// TIA Portal project "sample_pnio_test" (V15)

(* hardware
DEVICE "GSD device_1"  GSD.Device.PN
   slot 0: "机架"  Rack  V1.0
   slot 0: "id3000"  MV-ID3XXX  MV-IXX
      slot 0: "MV-ID3XXX"  MV-ID3XXX
      slot 1: "Interface"  Interface
         slot 1: "Port 1"  Port 1
   slot 1: " Acquisition Status _1"   Acquisition Status 
      slot 0: " Acquisition Status"   Acquisition Status 
   slot 2: " Acquisition Control _1"   Acquisition Control 
      slot 0: " Acquisition Control"   Acquisition Control 
   slot 3: " Reads Result 64 bytes _1"   Reads Result 64 bytes 
      slot 0: " Reads Result 64 bytes"   Reads Result 64 bytes 
   slot 4: " User Data 64 bytes _1"  User Data 64 bytes
      slot 0: " User Data 64 bytes"  User Data 64 bytes
DEVICE "S71500/ET200MP station_1"  S7-1500 station
   slot 0: "导轨_0"  Rack  6ES7 590-1***0-0AA0
   slot 1: "PLC_1"  CPU 1511-1 PN  6ES7 511-1AK01-0AB0  V1.8
      slot 3: "CPU 显示_1"  6ES7591-1AA00-0AA0
*)

// ===== PLC "PLC_1"  CPU 1511-1 PN =====

VAR_GLOBAL   // PLC tag table "默认变量表"
   "Clock_Byte" AT %MB0 : Byte;
   "Clock_10Hz" AT %M0.0 : Bool;
   "Clock_5Hz" AT %M0.1 : Bool;
   "Clock_2.5Hz" AT %M0.2 : Bool;
   "Clock_2Hz" AT %M0.3 : Bool;
   "Clock_1.25Hz" AT %M0.4 : Bool;
   "Clock_1Hz" AT %M0.5 : Bool;
   "Clock_0.625Hz" AT %M0.6 : Bool;
   "Clock_0.5Hz" AT %M0.7 : Bool;
   "Tag_1" AT %M2.0 : Bool;
   "Tag_2" AT %MB3 : Byte;
   "Tag_3" AT %M2.1 : Bool;
   "Tag_4" AT %M2.2 : Bool;
END_VAR

VAR_GLOBAL   // PLC tag table "MV_ID_Tags"
   "Trigger Ready" AT %I0.0 : Bool;
   "Trigger Ack" AT %I0.1 : Bool;
   "Acquiring" AT %I0.2 : Bool;
   "Decoding" AT %I0.3 : Bool;
   "Results OK" AT %I0.4 : Bool;
   "Results NG" AT %I0.5 : Bool;
   "General Fault" AT %I0.7 : Bool;
   "Trigger Enable" AT %Q0.0 : Bool;
   "Trigger" AT %Q0.1 : Bool;
   "Results Ack" AT %Q0.2 : Bool;
   "Excute Command" AT %Q0.3 : Bool;
   "Clear Error" AT %Q0.7 : Bool;
   "Result Length" AT %IB1 : Byte;
   "Result Data0" AT %IB2 : Char;
   "Result Data1" AT %IB3 : Char;
   "Result Data2" AT %IB4 : Char;
   "Result Data3" AT %IB5 : Char;
   "Result Data4" AT %IB6 : Char;
   "Result Data5" AT %IB7 : Char;
   "Result Data6" AT %IB8 : Char;
   "Result Data7" AT %IB9 : Char;
   "Result Data8" AT %IB10 : Char;
   "Result Data9" AT %IB11 : Char;
   "Result Data10" AT %IB12 : Char;
   "Result Data11" AT %IB13 : Char;
   "Result Data12" AT %IB14 : Char;
   "Result Data13" AT %IB15 : Char;
   "Result Data14" AT %IB16 : Char;
   "Result Data15" AT %IB17 : Char;
END_VAR

DATA_BLOCK "MV_ID_Result"   // DB1
{ S7_Optimized_Access := 'FALSE' }
VERSION : 0.1
   VAR
      "Result Length" : Byte;
      "Result Data0" : Char;
      "Result Data1" : Char;
      "Result Data2" : Char;
      "Result Data3" : Char;
      "Result Data4" : Char;
      "Result Data5" : Char;
      "Result Data6" : Char;
      "Result Data7" : Char;
      "Result Data8" : Char;
      "Result Data9" : Char;
      "Result Data10" : Char;
      "Result Data11" : Char;
      "Result Data12" : Char;
      "Result Data13" : Char;
      "Result Data14" : Char;
      "Result Data15" : Char;
      "Result Data16" : Char;
      "Result Data17" : Char;
      "Result Data18" : Char;
      "Result Data19" : Char;
      "Result Data20" : Char;
      "Result Data21" : Char;
      "Result Data22" : Char;
      "Result Data23" : Char;
      "Result Data24" : Char;
      "Result Data25" : Char;
      "Result Data26" : Char;
      "Result Data27" : Char;
      "Result Data28" : Char;
      "Result Data29" : Char;
      "Result Data30" : Char;
      "Result Data31" : Char;
      "Result Data32" : Char;
      "Result Data33" : Char;
      "Result Data34" : Char;
      "Result Data35" : Char;
      "Result Data36" : Char;
      "Result Data37" : Char;
      "Result Data38" : Char;
      "Result Data39" : Char;
      "Result Data40" : Char;
      "Result Data41" : Char;
      "Result Data42" : Char;
      "Result Data43" : Char;
      "Result Data44" : Char;
      "Result Data45" : Char;
      "Result Data46" : Char;
      "Result Data47" : Char;
      "Result Data48" : Char;
      "Result Data49" : Char;
      "Result Data50" : Char;
      "Result Data51" : Char;
      "Result Data52" : Char;
      "Result Data53" : Char;
      "Result Data54" : Char;
      "Result Data55" : Char;
      "Result Data56" : Char;
      "Result Data57" : Char;
      "Result Data58" : Char;
      "Result Data59" : Char;
      "Result Data60" : Char;
      "Result Data61" : Char;
      "Result Data62" : Char;
      "Result Data63" : Char;
      "Result Data64" : Char;
   END_VAR
BEGIN
END_DATA_BLOCK

ORGANIZATION_BLOCK "Main"   // OB1, LAD, ProgramCycle
TITLE = "Main Program Sweep (Cycle)"
{ S7_Optimized_Access := 'TRUE' }
VERSION : 0.1
   VAR_INPUT
      Initial_Call : Bool;   // Initial call of this OB
      Remanence : Bool;   // =True, if remanent data are available
   END_VAR
   VAR_TEMP   // added for the SCL form of the ladder/FBD networks
      _w1 : Bool;
      _w2 : Bool;
   END_VAR
BEGIN

REGION Network 1: Enable the reader
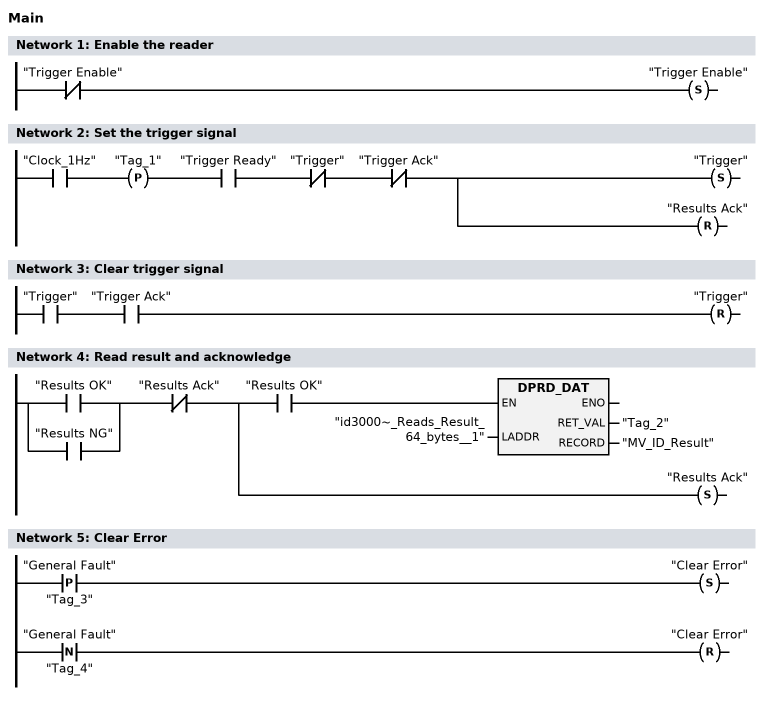
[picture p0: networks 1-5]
   RUNG wire#powerrail
      I_Contact( "Trigger Enable" )
      S_Coil( "Trigger Enable" )
   END_RUNG
   // the same network as SCL:
   IF NOT "Trigger Enable" THEN "Trigger Enable" := TRUE; END_IF;
END_REGION

REGION Network 2: Set the trigger signal
   RUNG wire#powerrail
      Contact( "Clock_1Hz" )
      P_Trig( "Tag_1" )
      Contact( "Trigger Ready" )
      I_Contact( "Trigger" )
      I_Contact( "Trigger Ack" )
      wire#w1
      S_Coil( "Trigger" )
   END_RUNG
   RUNG wire#w1
      R_Coil( "Results Ack" )
   END_RUNG
   // the same network as SCL:
   #_w1 := "Clock_1Hz" AND NOT "Tag_1";   // rising edge
   "Tag_1" := "Clock_1Hz";
   #_w2 := #_w1 AND "Trigger Ready" AND NOT "Trigger" AND NOT "Trigger Ack";
   IF #_w2 THEN
       "Trigger" := TRUE;
       "Results Ack" := FALSE;
   END_IF;
END_REGION

REGION Network 3: Clear trigger signal
   RUNG wire#powerrail
      Contact( "Trigger" )
      Contact( "Trigger Ack" )
      R_Coil( "Trigger" )
   END_RUNG
   // the same network as SCL:
   IF "Trigger" AND "Trigger Ack" THEN "Trigger" := FALSE; END_IF;
END_REGION

REGION Network 4: Read result and acknowledge
   #_w1 := ("Results OK" OR "Results NG") AND NOT "Results Ack";
   IF #_w1 AND "Results OK" THEN
       "Tag_2" := DPRD_DAT(LADDR := "id3000~_Reads_Result_64_bytes__1", RECORD => "MV_ID_Result");
   END_IF;
   IF #_w1 THEN "Results Ack" := TRUE; END_IF;
END_REGION

REGION Network 5: Clear Error
   RUNG wire#powerrail
      P_Contact(operand := "General Fault", bit := "Tag_3")
      S_Coil( "Clear Error" )
   END_RUNG
   RUNG wire#powerrail
      N_Contact(operand := "General Fault", bit := "Tag_4")
      R_Coil( "Clear Error" )
   END_RUNG
   // the same network as SCL:
   #_w1 := "General Fault" AND NOT "Tag_3";   // rising edge of "General Fault"
   "Tag_3" := "General Fault";
   IF #_w1 THEN "Clear Error" := TRUE; END_IF;
   #_w2 := NOT "General Fault" AND "Tag_4";   // falling edge of "General Fault"
   "Tag_4" := "General Fault";
   IF #_w2 THEN "Clear Error" := FALSE; END_IF;
END_REGION
END_ORGANIZATION_BLOCK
